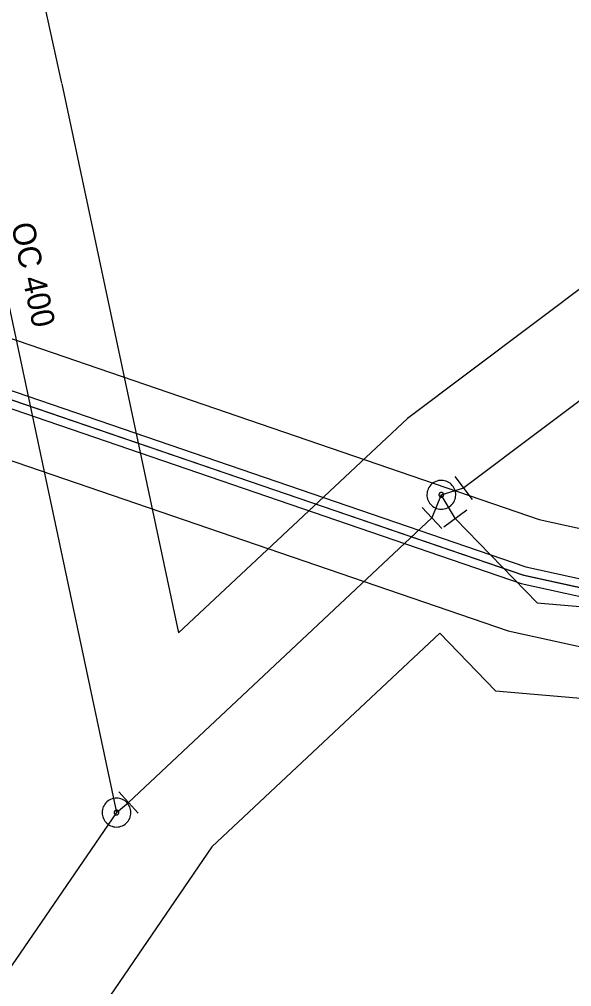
# Model space of a CAD drawing. Extents: x -762993 to -761845, y -975230 to -974501.
# Drawn here: x -762269.27 to -762259.7, y -975000.59 to -974983.83 of the extents above; entities that cross this region are included whole.
import ezdxf

# ---------------------------------------------------------------- set-up
doc = ezdxf.new("R2010")
doc.units = 0
for name, color, linetype in [('IS_CETIN_chranicka', 7, 'Continuous'), ('IS_CETIN_OP', 7, 'Continuous'), ('IS_CETIN_podzem optika zam', 7, 'Continuous'), ('IS_CRA_podzem telekomunikace', 7, 'Continuous'), ('IS_SCVK_vodovod anotace', 7, 'Continuous'), ('IS_SCVK_vodovod OP', 7, 'Continuous'), ('IS_SCVK_vodovod privadec', 7, 'Continuous'), ('IS_SCVK_vodovod znaky', 7, 'Continuous')]:
    doc.layers.add(name, color=color, linetype=linetype)

msp = doc.modelspace()

# ---------------------------------------------------------------- linework, layer by layer
at = {"layer": 'IS_CETIN_chranicka'}
for points in [[(-762286.819, -974981.848), (-762283.199, -974983.778), (-762274.07, -974988.662), (-762260.489, -974993.315), (-762251.575, -974995.272), (-762242.453, -974996.331)], [(-762286.961, -974982.112), (-762283.341, -974984.042), (-762274.19, -974988.938), (-762260.571, -974993.605), (-762251.625, -974995.568), (-762242.487, -974996.629)]]:
    msp.add_lwpolyline(points, dxfattribs=at)
at = {"layer": 'IS_CETIN_OP'}
for points in [[(-762282.633, -974983.117), (-762273.729, -974987.88), (-762260.26, -974992.495), (-762251.435, -974994.432), (-762246.779, -974994.973)], [(-762283.324, -974985.015), (-762274.531, -974989.72), (-762260.8, -974994.425), (-762251.765, -974996.408), (-762246.45, -974997.025)]]:
    msp.add_lwpolyline(points, dxfattribs=at)
at = {"layer": 'IS_CETIN_podzem optika zam'}
msp.add_lwpolyline([(-762274.13, -974988.8), (-762260.53, -974993.46), (-762251.6, -974995.42), (-762242.47, -974996.48), (-762240.63, -974996.21), (-762237.23, -974994.46), (-762217.903, -974996.032)], dxfattribs=at)
at = {"layer": 'IS_CRA_podzem telekomunikace'}
msp.add_lwpolyline([(-762276.159, -974987.718), (-762274.141, -974988.802), (-762260.544, -974993.454), (-762257.583, -974994.102)], dxfattribs=at)
at = {"layer": 'IS_SCVK_vodovod OP'}
for p, q in [((-762268.537, -974984.944), (-762266.512, -974994.461)), ((-762258.353, -974987.594), (-762262.542, -974990.741)), ((-762262.542, -974990.741), (-762266.512, -974994.461)), ((-762261.984, -974994.467), (-762265.932, -974998.166)), ((-762265.932, -974998.166), (-762273.888, -975009.773))]:
    msp.add_line(p, q, dxfattribs=at)
for points in [[(-762282.833, -974917.58), (-762281.112, -974927.652), (-762268.54, -974984.934)], [(-762261.984, -974994.467), (-762261.014, -974995.461), (-762257.933, -974995.728)]]:
    msp.add_lwpolyline(points, dxfattribs=at)
at = {"layer": 'IS_SCVK_vodovod privadec'}
for points in [[(-762270.2, -974985.298), (-762267.587, -974997.574)], [(-762257.344, -974988.775), (-762261.568, -974991.948)], [(-762262.118, -974992.468), (-762267.379, -974997.398)], [(-762261.712, -974992.482), (-762260.293, -974993.938), (-762257.797, -974994.154)], [(-762267.587, -974997.574), (-762275.202, -975008.684)]]:
    msp.add_lwpolyline(points, dxfattribs=at)
at = {"layer": 'IS_SCVK_vodovod znaky'}
for points in [[(-762261.716, -974991.993), (-762261.726, -974991.969), (-762261.737, -974991.945), (-762261.751, -974991.923), (-762261.767, -974991.903), (-762261.785, -974991.883), (-762261.805, -974991.867), (-762261.827, -974991.852), (-762261.85, -974991.84), (-762261.873, -974991.83), (-762261.899, -974991.823), (-762261.925, -974991.818), (-762261.951, -974991.816), (-762261.977, -974991.817), (-762262.003, -974991.821), (-762262.029, -974991.827), (-762262.052, -974991.836), (-762262.077, -974991.847), (-762262.099, -974991.861), (-762262.119, -974991.877), (-762262.138, -974991.895), (-762262.155, -974991.915), (-762262.17, -974991.937), (-762262.182, -974991.96), (-762262.192, -974991.984), (-762262.199, -974992.009), (-762262.204, -974992.035), (-762262.206, -974992.061), (-762262.205, -974992.087), (-762262.201, -974992.113), (-762262.195, -974992.139), (-762262.186, -974992.163), (-762262.175, -974992.187), (-762262.161, -974992.209), (-762262.145, -974992.229), (-762262.127, -974992.248), (-762262.107, -974992.265), (-762262.085, -974992.28), (-762262.062, -974992.293), (-762262.038, -974992.302), (-762262.013, -974992.309), (-762261.986, -974992.314), (-762261.961, -974992.316), (-762261.935, -974992.315), (-762261.909, -974992.311), (-762261.883, -974992.305), (-762261.859, -974992.296), (-762261.835, -974992.285), (-762261.813, -974992.271), (-762261.792, -974992.255), (-762261.774, -974992.236), (-762261.757, -974992.217), (-762261.742, -974992.196), (-762261.73, -974992.173), (-762261.72, -974992.148), (-762261.713, -974992.123), (-762261.708, -974992.097), (-762261.706, -974992.071), (-762261.707, -974992.045), (-762261.711, -974992.019), (-762261.716, -974991.993)], [(-762261.417, -974992.148), (-762261.718, -974991.748)], [(-762261.917, -974992.054), (-762261.918, -974992.05), (-762261.92, -974992.046), (-762261.922, -974992.043), (-762261.925, -974992.039), (-762261.927, -974992.036), (-762261.931, -974992.033), (-762261.935, -974992.03), (-762261.939, -974992.029), (-762261.943, -974992.027), (-762261.947, -974992.026), (-762261.951, -974992.025), (-762261.955, -974992.025), (-762261.959, -974992.025), (-762261.964, -974992.025), (-762261.968, -974992.027), (-762261.972, -974992.028), (-762261.976, -974992.03), (-762261.979, -974992.032), (-762261.983, -974992.035), (-762261.986, -974992.038), (-762261.989, -974992.041), (-762261.991, -974992.045), (-762261.993, -974992.049), (-762261.995, -974992.052), (-762261.996, -974992.057), (-762261.997, -974992.061), (-762261.997, -974992.065), (-762261.997, -974992.069), (-762261.997, -974992.074), (-762261.995, -974992.078), (-762261.993, -974992.082), (-762261.992, -974992.086), (-762261.99, -974992.089), (-762261.987, -974992.093), (-762261.984, -974992.096), (-762261.981, -974992.099), (-762261.977, -974992.101), (-762261.973, -974992.103), (-762261.969, -974992.105), (-762261.965, -974992.106), (-762261.961, -974992.106), (-762261.957, -974992.106), (-762261.953, -974992.106), (-762261.948, -974992.106), (-762261.944, -974992.105), (-762261.939, -974992.104), (-762261.936, -974992.101), (-762261.932, -974992.1), (-762261.929, -974992.097), (-762261.926, -974992.094), (-762261.923, -974992.091), (-762261.921, -974992.087), (-762261.919, -974992.083), (-762261.917, -974992.079), (-762261.916, -974992.075), (-762261.915, -974992.071), (-762261.915, -974992.067), (-762261.915, -974992.062), (-762261.915, -974992.058), (-762261.917, -974992.054)], [(-762261.956, -974992.066), (-762261.568, -974991.948)], [(-762261.956, -974992.066), (-762262.118, -974992.468)], [(-762261.712, -974992.482), (-762261.956, -974992.066)], [(-762261.947, -974992.65), (-762262.289, -974992.285)], [(-762261.511, -974992.333), (-762261.913, -974992.63)], [(-762267.548, -974997.214), (-762267.21, -974997.582)], [(-762267.535, -974997.819), (-762267.51, -974997.812), (-762267.485, -974997.802), (-762267.462, -974997.79), (-762267.44, -974997.776), (-762267.42, -974997.76), (-762267.401, -974997.741), (-762267.385, -974997.721), (-762267.371, -974997.699), (-762267.359, -974997.676), (-762267.349, -974997.651), (-762267.342, -974997.626), (-762267.339, -974997.6), (-762267.337, -974997.574), (-762267.339, -974997.548), (-762267.342, -974997.522), (-762267.349, -974997.497), (-762267.359, -974997.472), (-762267.371, -974997.449), (-762267.385, -974997.427), (-762267.401, -974997.407), (-762267.42, -974997.388), (-762267.44, -974997.372), (-762267.462, -974997.357), (-762267.485, -974997.345), (-762267.51, -974997.336), (-762267.535, -974997.329), (-762267.561, -974997.325), (-762267.587, -974997.324), (-762267.613, -974997.326), (-762267.639, -974997.329), (-762267.664, -974997.336), (-762267.689, -974997.346), (-762267.712, -974997.357), (-762267.734, -974997.372), (-762267.754, -974997.388), (-762267.773, -974997.406), (-762267.789, -974997.427), (-762267.804, -974997.449), (-762267.816, -974997.472), (-762267.824, -974997.497), (-762267.832, -974997.522), (-762267.836, -974997.548), (-762267.837, -974997.574), (-762267.835, -974997.6), (-762267.832, -974997.626), (-762267.824, -974997.65), (-762267.815, -974997.676), (-762267.804, -974997.699), (-762267.789, -974997.721), (-762267.773, -974997.741), (-762267.755, -974997.76), (-762267.734, -974997.775), (-762267.712, -974997.79), (-762267.689, -974997.802), (-762267.664, -974997.812), (-762267.639, -974997.819), (-762267.614, -974997.822), (-762267.587, -974997.824), (-762267.561, -974997.822), (-762267.535, -974997.819)], [(-762267.587, -974997.574), (-762267.379, -974997.398)], [(-762267.578, -974997.614), (-762267.574, -974997.613), (-762267.57, -974997.611), (-762267.567, -974997.61), (-762267.563, -974997.607), (-762267.56, -974997.604), (-762267.557, -974997.601), (-762267.554, -974997.598), (-762267.551, -974997.595), (-762267.55, -974997.591), (-762267.548, -974997.587), (-762267.547, -974997.582), (-762267.546, -974997.578), (-762267.546, -974997.574), (-762267.546, -974997.57), (-762267.547, -974997.565), (-762267.547, -974997.561), (-762267.55, -974997.557), (-762267.551, -974997.554), (-762267.554, -974997.55), (-762267.557, -974997.547), (-762267.56, -974997.544), (-762267.562, -974997.541), (-762267.566, -974997.538), (-762267.57, -974997.536), (-762267.574, -974997.535), (-762267.579, -974997.534), (-762267.583, -974997.533), (-762267.587, -974997.533), (-762267.591, -974997.533), (-762267.596, -974997.534), (-762267.6, -974997.535), (-762267.604, -974997.537), (-762267.607, -974997.538), (-762267.611, -974997.541), (-762267.614, -974997.544), (-762267.617, -974997.546), (-762267.62, -974997.55), (-762267.623, -974997.553), (-762267.625, -974997.557), (-762267.626, -974997.561), (-762267.627, -974997.566), (-762267.628, -974997.57), (-762267.628, -974997.574), (-762267.628, -974997.578), (-762267.627, -974997.583), (-762267.626, -974997.587), (-762267.624, -974997.591), (-762267.623, -974997.594), (-762267.62, -974997.598), (-762267.617, -974997.601), (-762267.615, -974997.604), (-762267.611, -974997.607), (-762267.608, -974997.61), (-762267.604, -974997.611), (-762267.6, -974997.613), (-762267.595, -974997.614), (-762267.591, -974997.615), (-762267.587, -974997.615), (-762267.583, -974997.615), (-762267.578, -974997.614)]]:
    msp.add_lwpolyline(points, dxfattribs=at)

# ---------------------------------------------------------------- texts
at = {"layer": 'IS_SCVK_vodovod anotace'}
msp.add_text('OC 400', height=0.4, rotation=282, dxfattribs=at).set_placement((-762269.416, -974987.388))

doc.saveas('drawing.dxf')
